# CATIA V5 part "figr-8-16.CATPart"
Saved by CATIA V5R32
Part number: Part1
Bounding box of the stored display mesh (mm): x -55.501 to 55.501, y -84.223 to 84.223, z 0 to 81
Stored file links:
  D:\PROJECTS\Project 2022\CATIA V5 6R 2022\Resources\Part Files\c08_catia_v5_6r2022_prt\figr-8-16.CATPart
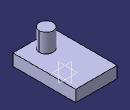
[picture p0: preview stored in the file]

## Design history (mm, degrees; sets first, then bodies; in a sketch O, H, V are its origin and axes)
Body1 (main body)
  Sketch1 on xy-plane, origin (0, 0, 0), H (1, 0, 0), V (0, 1, 0)
    line L1 (-55.501, 84.2232) -> (55.501, 84.2232)
    line L2 (55.501, 84.2232) -> (55.501, -84.2232)
    line L3 (55.501, -84.2232) -> (-55.501, -84.2232)
    line L4 (-55.501, -84.2232) -> (-55.501, 84.2232)
    axis line L5 (55.501, -84.2232) -> (-55.501, 84.2232)
    horizontal: L1 H, L3 H
    vertical: L2 V, L4 V
    midpoint: O L5
  Pad1: profile Sketch1, direction (0, 0, 1), length 31
  Sketch2 on face of Pad1, origin (0, 0, 31), H (1, 0, 0), V (0, 1, 0)
    circle A1 centre (0, -50.4568) radius 18.9426
    point P1 (0, -50.4568)
    coincidence: P1 V
  Pad2: profile Sketch2, direction (0, 0, 1), length 50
